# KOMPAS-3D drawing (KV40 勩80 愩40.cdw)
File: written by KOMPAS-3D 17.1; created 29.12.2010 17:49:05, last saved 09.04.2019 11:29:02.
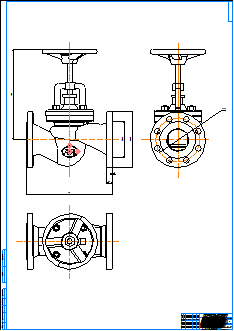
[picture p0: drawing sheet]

Title block, sheet 1: name: KV 40 Ду80; material: Внимание! Данный продукт является объектом авторского права ООО «Торговый Дом АДЛ». / Запрещается изменение, копирование, распространение / (в том числе путем копирования на другие сайты и ресурсы в Интернете) / или любое иное использование информации и объектов без предварительного / согласия правообладателя (ООО «Торговый Дом АДЛ»).; scale: 1:1; sheets: 1; organisation: ООО "Торговый дом АДЛ"; sheet format: A0; stored path: \\adlc.lan\data\АДЛ_ПКД\3D-модели\ADL production\Вентили ГРАНВЕНТ\KV40\KOMPAS 2D\KV 40 Ду80.cdw

Views: Спереди 1, Проекционный вид 3, Вид 6
Dimensions and other numbers on the sheet: 3; 22; 138; 200; 310; 160; 325; 1:1; 1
